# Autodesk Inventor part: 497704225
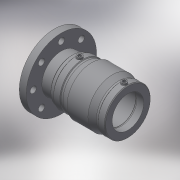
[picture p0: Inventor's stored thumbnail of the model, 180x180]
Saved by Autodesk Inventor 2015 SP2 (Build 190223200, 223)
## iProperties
Created: 2017-06
Part Number: 497704225
Material: Generic
Description: PLASSON PE CAST IRON SPIGOT COUPLER TRANSITION 225-200
Document SubType Name: Modeling
Designer: KIM
Mass: 55.0731 g
Surface Area: 148.067 cm^2
Volume: 55.0731 cm^3
Density: 1 g/cm^3
Appearance: Default
Author: KIM
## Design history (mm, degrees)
derived "497704.ipt"
feature "Solid1::497704.ipt"
tag "TaggingFeature1"
body "Solid1"
other parameters: "d14" = 17.6296, "d15" = 119, "d16" = 119, "d17" = 213.75, "d18" = 225, "d19" = 3.52592, "d20" = 168 deg, "d22" = 253.8, "d24" = 246.186, "d25" = 135 deg, "d26" = 96, "d27" = 135 deg, "d29" = 138, "d35" = 15, "d39" = 5 deg, "d45" = 4, "d46" = 14, "d47" = 0, "d50" = 3, "d51" = 0, "d52" = 34.51, "d53" = 8.6275, "d55" = 0.1, "d56" = 240.3, "d58" = 74, "d60" = 176, "d62" = 8.1, "d65" = 5.4, "d70" = 26, "d71" = 8.66667, "d72" = 216.27, "d73" = 15.6, "d74" = 22, "d75" = 147.5, "d77" = 0, "d79" = 360 deg, "d_" = 225, "L_" = 314, "L_1" = 119, "A_" = 138, "d_2" = 12, "L_2" = 74, "H_" = 109, "d_1" = 176, "t_" = 26, "S_" = 22, "D_p" = 295
